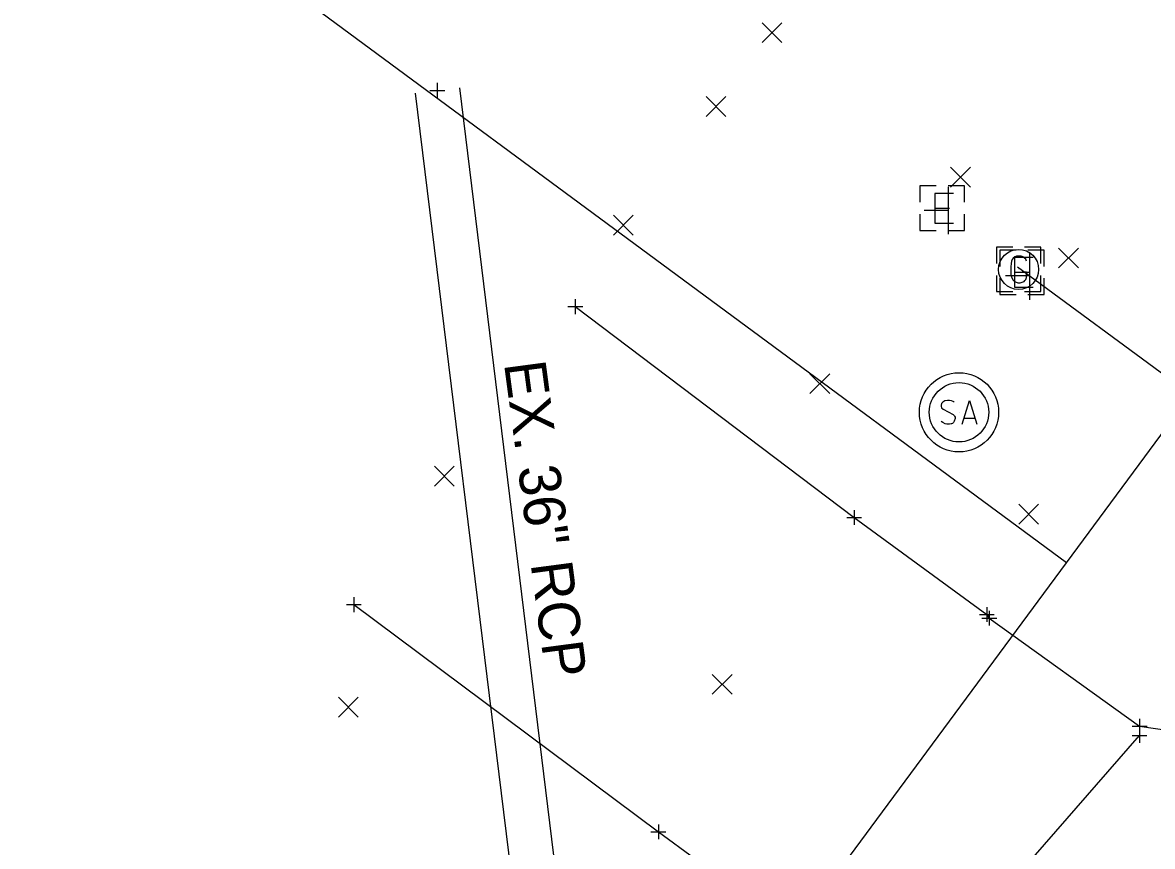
# Model space of a CAD drawing. Extents: x 1324089 to 1329959, y 459099 to 462017.
# Drawn here: x 1325717.7 to 1325793.8, y 460994.4 to 461050 of the extents above; entities that cross this region are included whole.
import ezdxf

# ---------------------------------------------------------------- set-up
doc = ezdxf.new("R2010")
doc.units = 0
for name, color, linetype in [('Default', 7, 'Continuous'), ('DR_X_Elev_Flow', 7, 'Continuous'), ('DR_X_Storm_Sewer', 7, 'Continuous'), ('DV_X_Property_Line', 7, 'Continuous'), ('GK_Drainage_Nodes', 7, 'Continuous'), ('PV_X_Driveway', 7, 'Continuous'), ('RW_X_Fee_RW', 7, 'Continuous'), ('SN_X_Public', 7, 'Continuous'), ('SV_X_Random_Point', 7, 'Continuous'), ('SV_X_Shot_Marker', 7, 'Continuous'), ('UT_X_Electric_Cells', 7, 'Continuous'), ('UT_X_Gas', 7, 'Continuous'), ('UT_X_Gas_Cells', 7, 'Continuous'), ('UT_X_Sanitary_Cells', 7, 'Continuous'), ('UT_X_Telecom', 7, 'Continuous')]:
    doc.layers.add(name, color=color, linetype=linetype)

msp = doc.modelspace()

# ---------------------------------------------------------------- linework, layer by layer
at = {"layer": 'DR_X_Elev_Flow'}
for p, q in [((1325745.15, 461045.389), (1325746.15, 461045.389)), ((1325745.65, 461045.889), (1325745.65, 461044.889)), ((1325745.65, 461045.389), (1325745.65, 461045.389))]:
    msp.add_line(p, q, dxfattribs=at)
at = {"layer": 'DR_X_Storm_Sewer'}
for p, q in [((1325747.138, 461045.572), (1325755.043, 460981.125)), ((1325744.161, 461045.207), (1325752.065, 460980.759)), ((1325744.161, 461045.207), (1325752.065, 460980.759))]:
    msp.add_line(p, q, dxfattribs=at)
at = {"layer": 'DV_X_Property_Line'}
msp.add_line((1325788.031, 461013.559), (1325636.381, 461125.517), dxfattribs=at)
at = {"layer": 'GK_Drainage_Nodes'}
for p, q in [((1325780.798, 461025.699), (1325780.798, 461025.699)), ((1325780.798, 461023.699), (1325780.798, 461023.699)), ((1325780.798, 461023.699), (1325780.798, 461023.699)), ((1325780.798, 461023.699), (1325780.798, 461023.699)), ((1325780.798, 461021.699), (1325780.798, 461021.699))]:
    msp.add_line(p, q, dxfattribs=at)
msp.add_circle((1325780.798, 461023.699), 2, dxfattribs=at)
at = {"layer": 'PV_X_Driveway'}
for points in [[(1325754.943, 461030.819), (1325773.732, 461016.608), (1325782.671, 461010.077), (1325782.835, 461009.831), (1325792.965, 461002.54), (1325804.673, 461000.844), (1325812.487, 460999.802), (1325816.225, 460999.305)], [(1325740.02, 461010.738), (1325760.541, 460995.43), (1325777.688, 460982.844), (1325779.255, 460964.921), (1325780.318, 460951.923)]]:
    msp.add_lwpolyline(points, dxfattribs=at)
at = {"layer": 'RW_X_Fee_RW'}
msp.add_line((1325448.762, 460554.274), (1326011.051, 461315.471), dxfattribs=at)
at = {"layer": 'SN_X_Public'}
for p, q in [((1325780.058, 461038.898), (1325780.058, 461035.698)), ((1325780.058, 461037.298), (1325778.458, 461037.298)), ((1325780.057, 461037.299), (1325780.057, 461037.299)), ((1325785.54, 461034.487), (1325785.54, 461031.287)), ((1325785.54, 461032.887), (1325783.94, 461032.887)), ((1325785.539, 461032.888), (1325785.539, 461032.888))]:
    msp.add_line(p, q, dxfattribs=at)
at = {"layer": 'SV_X_Random_Point'}
for p, q in [((1325767.528, 461048.615), (1325768.861, 461049.95)), ((1325767.528, 461049.95), (1325768.861, 461048.615)), ((1325763.763, 461043.633), (1325765.096, 461044.968)), ((1325763.763, 461044.968), (1325765.096, 461043.633)), ((1325780.234, 461038.87), (1325781.567, 461040.205)), ((1325780.234, 461040.205), (1325781.567, 461038.87)), ((1325757.519, 461035.635), (1325758.852, 461036.97)), ((1325757.519, 461036.97), (1325758.852, 461035.635)), ((1325787.507, 461033.426), (1325788.84, 461034.76)), ((1325787.507, 461034.76), (1325788.84, 461033.426)), ((1325770.754, 461024.957), (1325772.087, 461026.292)), ((1325770.754, 461026.292), (1325772.087, 461024.957)), ((1325745.454, 461018.725), (1325746.787, 461020.06)), ((1325745.454, 461020.06), (1325746.787, 461018.725)), ((1325784.823, 461016.163), (1325786.157, 461017.498)), ((1325784.823, 461017.498), (1325786.157, 461016.163)), ((1325764.173, 461004.696), (1325765.506, 461006.031)), ((1325764.173, 461006.031), (1325765.506, 461004.696)), ((1325738.983, 461003.165), (1325740.317, 461004.499)), ((1325738.983, 461004.499), (1325740.317, 461003.165))]:
    msp.add_line(p, q, dxfattribs=at)
at = {"layer": 'SV_X_Shot_Marker'}
for p, q in [((1325754.943, 461031.319), (1325754.943, 461030.319)), ((1325754.443, 461030.819), (1325755.443, 461030.819)), ((1325754.943, 461030.819), (1325754.943, 461030.819)), ((1325773.232, 461016.608), (1325774.232, 461016.608)), ((1325773.732, 461017.108), (1325773.732, 461016.108)), ((1325773.732, 461016.608), (1325773.732, 461016.608)), ((1325740.02, 461011.238), (1325740.02, 461010.238)), ((1325739.52, 461010.738), (1325740.52, 461010.738)), ((1325740.02, 461010.738), (1325740.02, 461010.738)), ((1325782.671, 461010.577), (1325782.671, 461009.577)), ((1325782.835, 461010.331), (1325782.835, 461009.331)), ((1325782.171, 461010.077), (1325783.171, 461010.077)), ((1325782.335, 461009.831), (1325783.335, 461009.831)), ((1325782.671, 461010.077), (1325782.671, 461010.077)), ((1325782.835, 461009.831), (1325782.835, 461009.831)), ((1325792.965, 461003.04), (1325792.965, 461002.04)), ((1325792.465, 461002.54), (1325793.465, 461002.54)), ((1325792.957, 461002.421), (1325792.957, 461001.421)), ((1325792.965, 461002.54), (1325792.965, 461002.54)), ((1325792.457, 461001.921), (1325793.457, 461001.921)), ((1325792.957, 461001.921), (1325792.957, 461001.921)), ((1325760.541, 460995.93), (1325760.541, 460994.93)), ((1325760.041, 460995.43), (1325761.041, 460995.43)), ((1325760.541, 460995.43), (1325760.541, 460995.43))]:
    msp.add_line(p, q, dxfattribs=at)
at = {"layer": 'UT_X_Electric_Cells'}
for p, q in [((1325779.166, 461037.452), (1325780.166, 461037.452)), ((1325779.666, 461037.452), (1325779.666, 461037.452)), ((1325784.542, 461033.133), (1325785.542, 461033.133)), ((1325785.042, 461033.133), (1325785.042, 461033.133))]:
    msp.add_line(p, q, dxfattribs=at)
for points in [[(1325779.266, 461038.952), (1325778.166, 461038.952), (1325778.166, 461037.852)], [(1325781.166, 461037.852), (1325781.166, 461038.952), (1325780.066, 461038.952)], [(1325780.416, 461038.452), (1325779.166, 461038.452), (1325779.166, 461036.452), (1325780.416, 461036.452)], [(1325778.166, 461037.052), (1325778.166, 461035.952), (1325779.266, 461035.952)], [(1325780.066, 461035.952), (1325781.166, 461035.952), (1325781.166, 461037.052)], [(1325784.642, 461034.633), (1325783.542, 461034.633), (1325783.542, 461033.533)], [(1325785.792, 461034.133), (1325784.542, 461034.133), (1325784.542, 461032.133), (1325785.792, 461032.133)], [(1325786.542, 461033.533), (1325786.542, 461034.633), (1325785.442, 461034.633)], [(1325783.542, 461032.733), (1325783.542, 461031.633), (1325784.642, 461031.633)], [(1325785.442, 461031.633), (1325786.542, 461031.633), (1325786.542, 461032.733)]]:
    msp.add_lwpolyline(points, dxfattribs=at)
at = {"layer": 'UT_X_Gas'}
msp.add_line((1325784.747, 461033.499), (1325843.475, 460990.142), dxfattribs=at)
at = {"layer": 'UT_X_Gas_Cells'}
msp.add_line((1325784.814, 461033.327), (1325784.814, 461033.327), dxfattribs=at)
for points in [[(1325784.414, 461034.827), (1325783.314, 461034.827), (1325783.314, 461033.727)], [(1325786.314, 461033.727), (1325786.314, 461034.827), (1325785.214, 461034.827)], [(1325785.347, 461033.873), (1325785.333, 461033.944), (1325785.29, 461034.015), (1325785.219, 461034.086), (1325785.12, 461034.171), (1325785.049, 461034.199), (1325784.992, 461034.213), (1325784.907, 461034.227), (1325784.737, 461034.227), (1325784.667, 461034.213), (1325784.624, 461034.199), (1325784.567, 461034.171), (1325784.454, 461034.086), (1325784.383, 461033.986), (1325784.341, 461033.873), (1325784.312, 461033.717), (1325784.284, 461033.491), (1325784.284, 461033.193), (1325784.298, 461032.952), (1325784.355, 461032.768), (1325784.44, 461032.598), (1325784.511, 461032.541), (1325784.596, 461032.484), (1325784.752, 461032.427), (1325784.907, 461032.427), (1325785.063, 461032.456), (1325785.12, 461032.484), (1325785.177, 461032.513), (1325785.234, 461032.569), (1325785.29, 461032.654), (1325785.347, 461032.782), (1325785.347, 461033.136), (1325785.049, 461033.136)], [(1325783.314, 461032.927), (1325783.314, 461031.827), (1325784.414, 461031.827)], [(1325785.214, 461031.827), (1325786.314, 461031.827), (1325786.314, 461032.927)]]:
    msp.add_lwpolyline(points, dxfattribs=at)
msp.add_circle((1325784.814, 461033.327), 1.35, dxfattribs=at)
at = {"layer": 'UT_X_Sanitary_Cells'}
for points in [[(1325780.466, 461024.386), (1325780.441, 461024.411), (1325780.403, 461024.436), (1325780.289, 461024.474), (1325780.151, 461024.499), (1325780.05, 461024.499), (1325780.012, 461024.499), (1325779.848, 461024.462), (1325779.71, 461024.386), (1325779.622, 461024.285), (1325779.597, 461024.184), (1325779.597, 461024.109), (1325779.622, 461024.008), (1325779.722, 461023.92), (1325780.415, 461023.542), (1325780.478, 461023.492), (1325780.504, 461023.441), (1325780.529, 461023.366), (1325780.529, 461023.29), (1325780.516, 461023.214), (1325780.504, 461023.164), (1325780.478, 461023.101), (1325780.453, 461023.051), (1325780.428, 461023.013), (1325780.39, 461022.975), (1325780.352, 461022.95), (1325780.302, 461022.925), (1325780.264, 461022.912), (1325780.151, 461022.899), (1325779.974, 461022.899), (1325779.861, 461022.925), (1325779.697, 461023.013), (1325779.597, 461023.088)], [(1325781.007, 461022.899), (1325781.511, 461024.499), (1325782.003, 461022.899)], [(1325781.877, 461023.277), (1325781.133, 461023.277)]]:
    msp.add_lwpolyline(points, dxfattribs=at)
for radius in [2.667, 2]:
    msp.add_circle((1325780.798, 461023.699), radius, dxfattribs=at)
at = {"layer": 'UT_X_Telecom'}
msp.add_lwpolyline([(1325738.74, 460932.483), (1325743.645, 460940.13), (1325749.252, 460948.815), (1325753.874, 460954.188), (1325760.392, 460962.64), (1325766.576, 460970.181), (1325777.411, 460984.097), (1325792.957, 461001.921)], dxfattribs=at)

# ---------------------------------------------------------------- texts
at = {"layer": 'Default'}
msp.add_text('EX. 36" RCP', height=2.8, rotation=277.5723, dxfattribs=at).set_placement((1325750.137, 461026.993))

doc.saveas('drawing.dxf')
